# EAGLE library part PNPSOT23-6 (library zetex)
PNP TRANSISTOR
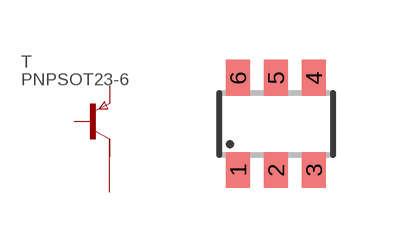
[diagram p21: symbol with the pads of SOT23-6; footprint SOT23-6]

Designator prefix T

## PNPSOT23-6 (MPN: ZXT13P12DE6; OC_FARNELL: 1471192RL; OC_NEWARK: 70K9269)  [SOT23-6]
1  C  pas
2  C1  pas
3  B  pas
4  E  pas
5  C2  pas
6  C3  pas

## Footprint SOT23-6 (pad centres in mm)
Small Outline Transistor 6 lead
smd 0.6 x 0.9: 1 -0.95,-1.15; 2 0,-1.15; 3 0.95,-1.15; 4 0.95,1.15; 5 0,1.15; 6 -0.95,1.15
